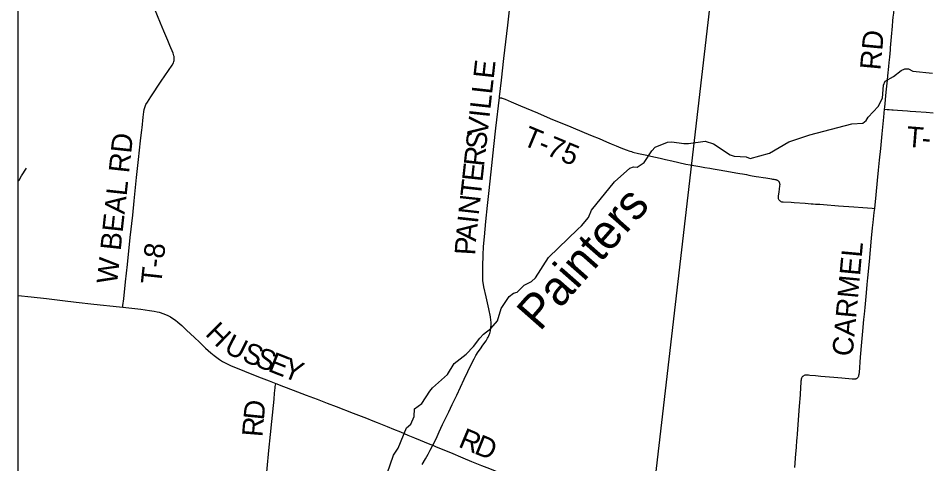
# Model space of a CAD drawing. Extents: x -49 to -8.2, y 9.4 to 23.5.
# Drawn here: x -14.966 to -13.706, y 10.403 to 11.018 of the extents above; entities that cross this region are included whole.
import ezdxf

# ---------------------------------------------------------------- set-up
doc = ezdxf.new("R2010")
doc.units = 0
for name, color, linetype in [('GM_X_Adjacent_County', 7, 'Continuous'), ('GM_X_County_Road', 7, 'Continuous'), ('GM_X_County_Road_Text', 7, 'Continuous'), ('GM_X_Minor_River', 7, 'Continuous'), ('GM_X_Minor_River_Text', 7, 'Continuous'), ('GM_X_Township_Road', 7, 'Continuous'), ('GM_X_Township_Road_Text', 7, 'Continuous')]:
    doc.layers.add(name, color=color, linetype=linetype)

msp = doc.modelspace()

# ---------------------------------------------------------------- linework, layer by layer
at = {"layer": 'GM_X_Adjacent_County'}
msp.add_lwpolyline([(-14.9662, 16.2087), (-8.1662, 16.2087), (-8.1662, 9.4087), (-14.9662, 9.4087)], close=True, dxfattribs=at)
msp.add_lwpolyline([(-14.005, 11.0879), (-14.0954, 10.3092), (-14.1248, 9.8722), (-14.156, 9.4087)], dxfattribs=at)
at = {"layer": 'GM_X_County_Road'}
for points in [[(-14.3018, 10.9084), (-14.3017, 10.9095), (-14.299, 10.9324), (-14.2954, 10.9626), (-14.29, 11.0083), (-14.2878, 11.029), (-14.2813, 11.0873), (-14.2771, 11.1259), (-14.2722, 11.171), (-14.2684, 11.205), (-14.2653, 11.2325), (-14.2624, 11.2587), (-14.258, 11.2986), (-14.2572, 11.3066)], [(-13.7697, 10.8924), (-13.7694, 10.895), (-13.7674, 10.916), (-13.7659, 10.9324), (-13.7653, 10.9386), (-13.764, 10.9512), (-13.7634, 10.9571), (-13.7627, 10.9642), (-13.7617, 10.9744), (-13.7614, 10.9772), (-13.7597, 10.9973), (-13.7593, 11.002), (-13.7588, 11.0072), (-13.7582, 11.0146), (-13.7578, 11.0193), (-13.7572, 11.0252), (-13.7562, 11.036), (-13.7553, 11.0455), (-13.7541, 11.0574)], [(-14.3937, 10.4284), (-14.3904, 10.4348), (-14.3877, 10.4407), (-14.3848, 10.4469), (-14.3801, 10.457), (-14.3717, 10.4747), (-14.3669, 10.4848), (-14.3607, 10.4977), (-14.3502, 10.5198), (-14.3453, 10.5302), (-14.3396, 10.542), (-14.3366, 10.5478), (-14.3341, 10.5523), (-14.331, 10.5575), (-14.3279, 10.5618), (-14.3244, 10.5666), (-14.3202, 10.5727), (-14.318, 10.5764), (-14.3171, 10.5778), (-14.3163, 10.5795), (-14.3158, 10.5809), (-14.3151, 10.5829), (-14.3146, 10.5845), (-14.3141, 10.5864), (-14.3138, 10.5881), (-14.3134, 10.5904), (-14.3131, 10.5947), (-14.313, 10.5964), (-14.3131, 10.5983), (-14.3134, 10.6014), (-14.3141, 10.606), (-14.3164, 10.6166), (-14.3202, 10.6336), (-14.3231, 10.6472), (-14.3241, 10.6531), (-14.3244, 10.6556), (-14.3246, 10.6577), (-14.3248, 10.6627), (-14.3246, 10.6758), (-14.3242, 10.691), (-14.3236, 10.7031), (-14.3225, 10.7162), (-14.3204, 10.7375), (-14.3181, 10.7594), (-14.316, 10.7801), (-14.3121, 10.8147), (-14.3092, 10.841), (-14.3065, 10.866), (-14.3018, 10.9084)], [(-13.7834, 10.7554), (-13.7814, 10.7744), (-13.7794, 10.7942), (-13.7781, 10.8081), (-13.7766, 10.822), (-13.775, 10.8381), (-13.7729, 10.8585), (-13.7707, 10.8814), (-13.7697, 10.8924)], [(-13.8937, 10.3977), (-13.8923, 10.4166), (-13.8916, 10.4252), (-13.8908, 10.4355), (-13.8906, 10.4379), (-13.8902, 10.4444), (-13.8872, 10.4825), (-13.886, 10.4983), (-13.8854, 10.5086), (-13.885, 10.5148), (-13.8849, 10.5176), (-13.8847, 10.5187), (-13.8845, 10.5201), (-13.8841, 10.5216), (-13.8836, 10.5227), (-13.883, 10.5234), (-13.8824, 10.5241), (-13.8817, 10.5246), (-13.8811, 10.5249), (-13.8805, 10.5252), (-13.8794, 10.5255), (-13.8781, 10.5257), (-13.8767, 10.5257), (-13.875, 10.5256), (-13.8729, 10.5253), (-13.8651, 10.5246), (-13.858, 10.524), (-13.84, 10.5225), (-13.8286, 10.5216), (-13.8143, 10.5202), (-13.8122, 10.5201), (-13.8103, 10.5202), (-13.8095, 10.5203), (-13.8088, 10.5206), (-13.8082, 10.5208), (-13.8075, 10.5212), (-13.807, 10.5216), (-13.8067, 10.5218), (-13.8063, 10.5225), (-13.8057, 10.5234), (-13.8055, 10.524), (-13.8052, 10.5251), (-13.8049, 10.5267), (-13.8045, 10.5291), (-13.8028, 10.5499), (-13.801, 10.571), (-13.7997, 10.5858), (-13.7982, 10.6019), (-13.7975, 10.6096), (-13.7966, 10.6186), (-13.7956, 10.6288), (-13.7947, 10.639), (-13.7936, 10.6504), (-13.7928, 10.6594), (-13.7908, 10.682), (-13.7878, 10.7145), (-13.7863, 10.7287), (-13.7855, 10.7361), (-13.784, 10.7497), (-13.7834, 10.7554)], [(-14.9662, 10.6353), (-14.9484, 10.6334), (-14.9271, 10.6309), (-14.9049, 10.6284), (-14.8864, 10.6262), (-14.862, 10.6234), (-14.8262, 10.6194), (-14.8218, 10.6189)], [(-14.8218, 10.6189), (-14.7971, 10.6162), (-14.7848, 10.6147), (-14.7787, 10.6137), (-14.7742, 10.6128), (-14.7716, 10.6122), (-14.77, 10.6117), (-14.7665, 10.6106), (-14.7627, 10.6091), (-14.7594, 10.6075), (-14.7561, 10.6057), (-14.7527, 10.6036), (-14.7492, 10.6011), (-14.7456, 10.5982), (-14.7405, 10.5937), (-14.7339, 10.5876), (-14.7227, 10.5772), (-14.7158, 10.5706), (-14.7074, 10.5627), (-14.7001, 10.556), (-14.6955, 10.5522), (-14.6921, 10.5495), (-14.6882, 10.5468), (-14.6843, 10.5443), (-14.6805, 10.5422), (-14.6768, 10.5403), (-14.672, 10.5382), (-14.6616, 10.534), (-14.6538, 10.5308), (-14.6342, 10.5229), (-14.6198, 10.5173), (-14.6104, 10.5138)], [(-14.6426, 10.2114), (-14.6409, 10.2244), (-14.6346, 10.2823), (-14.6303, 10.3221), (-14.6292, 10.3326), (-14.6276, 10.3481), (-14.6262, 10.361), (-14.6245, 10.3777), (-14.6225, 10.3966), (-14.62, 10.4213), (-14.6178, 10.4435), (-14.616, 10.4611), (-14.613, 10.4923), (-14.6122, 10.5004), (-14.6115, 10.5079), (-14.6113, 10.5098), (-14.611, 10.5114), (-14.6106, 10.5132), (-14.6104, 10.5138)], [(-14.6104, 10.5138), (-14.6, 10.5098), (-14.5864, 10.5046), (-14.5687, 10.4978), (-14.5536, 10.4921), (-14.5397, 10.4867), (-14.5272, 10.4819), (-14.5037, 10.4728), (-14.4853, 10.4657), (-14.4764, 10.4624), (-14.4707, 10.4601), (-14.4566, 10.4543), (-14.448, 10.4508), (-14.4382, 10.4468), (-14.4281, 10.4426), (-14.419, 10.4388), (-14.3978, 10.4301), (-14.3937, 10.4284)], [(-14.4084, 10.4018), (-14.4039, 10.4097), (-14.4002, 10.4161), (-14.3971, 10.4218), (-14.3937, 10.4284)], [(-14.3937, 10.4284), (-14.3892, 10.4265), (-14.3693, 10.4184), (-14.3521, 10.4112), (-14.3401, 10.4062), (-14.3266, 10.4007), (-14.3156, 10.3962), (-14.3076, 10.393), (-14.2945, 10.3878), (-14.2771, 10.3811), (-14.2556, 10.373), (-14.2295, 10.3631), (-14.2123, 10.3567), (-14.2027, 10.3531), (-14.1797, 10.3445), (-14.162, 10.3378), (-14.1306, 10.326), (-14.1094, 10.318), (-14.0942, 10.3124), (-14.093, 10.3119)]]:
    msp.add_lwpolyline(points, dxfattribs=at)
at = {"layer": 'GM_X_Minor_River'}
for points in [[(-14.0914, 10.8349), (-14.0865, 10.84), (-14.0695, 10.847), (-14.0634, 10.8475), (-14.0468, 10.8452), (-14.0405, 10.8449), (-14.0177, 10.8484), (-14.006, 10.8446), (-13.983, 10.8295), (-13.9774, 10.8274), (-13.9607, 10.8266), (-13.9556, 10.8244), (-13.9289, 10.8315), (-13.902, 10.8473), (-13.8729, 10.8571), (-13.8152, 10.872), (-13.7999, 10.8733), (-13.7951, 10.8766), (-13.7926, 10.8815), (-13.7787, 10.8962), (-13.7725, 10.9077), (-13.7712, 10.9257), (-13.769, 10.9312), (-13.7574, 10.9376), (-13.747, 10.9457), (-13.7417, 10.9481), (-13.7369, 10.948), (-13.7309, 10.9451), (-13.7036, 10.9421)], [(-14.4566, 10.3897), (-14.4481, 10.4148), (-14.4417, 10.4246), (-14.43, 10.4527), (-14.4241, 10.4578), (-14.4194, 10.4682), (-14.4189, 10.4788), (-14.409, 10.4861), (-14.3979, 10.503), (-14.3943, 10.5079), (-14.3732, 10.5264), (-14.3643, 10.5413), (-14.3478, 10.5542), (-14.3373, 10.5647), (-14.3286, 10.5763), (-14.3238, 10.5817), (-14.3135, 10.5896), (-14.3042, 10.6003), (-14.2993, 10.6173), (-14.2883, 10.6339), (-14.2823, 10.6383), (-14.2772, 10.6398), (-14.2674, 10.6497), (-14.2573, 10.6545), (-14.2517, 10.6594), (-14.2339, 10.6876), (-14.1935, 10.7268), (-14.1885, 10.7312), (-14.1788, 10.7427), (-14.1744, 10.7529), (-14.1428, 10.7923), (-14.1217, 10.8109), (-14.1167, 10.8127), (-14.1116, 10.8124), (-14.1017, 10.8188), (-14.0914, 10.8349)], [(-14.9662, 10.7932), (-14.9648, 10.7944), (-14.9619, 10.8002), (-14.9547, 10.8108)]]:
    msp.add_lwpolyline(points, dxfattribs=at)
at = {"layer": 'GM_X_Township_Road'}
for points in [[(-14.7955, 10.864), (-14.7952, 10.8667), (-14.7937, 10.8812), (-14.7928, 10.8889), (-14.7923, 10.8918), (-14.7919, 10.8934), (-14.7916, 10.8948), (-14.7911, 10.8962), (-14.7905, 10.8974), (-14.7899, 10.8987), (-14.7879, 10.9022), (-14.7833, 10.9096), (-14.7687, 10.9312), (-14.7538, 10.9534), (-14.7519, 10.9566), (-14.7512, 10.9582), (-14.7509, 10.9595), (-14.7508, 10.9604), (-14.7507, 10.9613), (-14.7507, 10.9623), (-14.7507, 10.9632), (-14.7508, 10.9641), (-14.751, 10.9651), (-14.7513, 10.9663), (-14.7523, 10.9696), (-14.7569, 10.9805), (-14.7598, 10.9874), (-14.7651, 11.0003), (-14.7698, 11.0114), (-14.778, 11.0316)], [(-14.3018, 10.9084), (-14.3013, 10.9083), (-14.2995, 10.908), (-14.299, 10.9079), (-14.2983, 10.9077), (-14.2978, 10.9075), (-14.2939, 10.9061), (-14.2856, 10.9026), (-14.2724, 10.8971), (-14.249, 10.8872), (-14.2315, 10.8798), (-14.2031, 10.868), (-14.1848, 10.8603), (-14.1738, 10.8558), (-14.1641, 10.8518), (-14.1538, 10.8474), (-14.1472, 10.8447), (-14.1403, 10.8418), (-14.134, 10.8392), (-14.1265, 10.8361), (-14.1215, 10.8344), (-14.1195, 10.8338), (-14.1174, 10.8332), (-14.1095, 10.8313), (-14.098, 10.8288), (-14.0925, 10.8275), (-14.0795, 10.8246), (-14.0725, 10.8231), (-14.0635, 10.8211), (-14.0444, 10.8167), (-14.0384, 10.8156), (-14.0379, 10.8155)], [(-13.7697, 10.8924), (-13.7662, 10.8922), (-13.7657, 10.8922), (-13.7648, 10.8921), (-13.7633, 10.892), (-13.7599, 10.8917), (-13.758, 10.8916), (-13.7518, 10.8911), (-13.7379, 10.89), (-13.7345, 10.8898), (-13.7267, 10.8892), (-13.7122, 10.8881), (-13.7026, 10.8873)], [(-14.8218, 10.6189), (-14.8216, 10.6212), (-14.8205, 10.6306), (-14.818, 10.6541), (-14.8154, 10.6779), (-14.8115, 10.7153), (-14.8081, 10.7462), (-14.8061, 10.7657), (-14.8027, 10.7981), (-14.8, 10.8231), (-14.7972, 10.8488), (-14.7955, 10.864)], [(-14.0379, 10.8155), (-14.0332, 10.8146), (-14.0248, 10.8132), (-14.018, 10.8121), (-14.0113, 10.811), (-14.0066, 10.8102), (-14.0009, 10.8091), (-13.9878, 10.8067), (-13.9751, 10.8045), (-13.9698, 10.8037), (-13.966, 10.803), (-13.9606, 10.8021), (-13.9573, 10.8015), (-13.9549, 10.801), (-13.9525, 10.8006), (-13.947, 10.7996), (-13.9434, 10.799), (-13.9375, 10.7981), (-13.9338, 10.7975), (-13.9283, 10.7966), (-13.9259, 10.7962), (-13.9246, 10.796), (-13.9225, 10.7957), (-13.9212, 10.7955), (-13.9201, 10.7952), (-13.9194, 10.795), (-13.9186, 10.7947), (-13.9179, 10.7944), (-13.9172, 10.794), (-13.9167, 10.7935), (-13.9163, 10.7931), (-13.9157, 10.7924), (-13.9155, 10.792), (-13.9152, 10.7913), (-13.9149, 10.7907), (-13.9147, 10.7898), (-13.9146, 10.7883), (-13.9147, 10.7867), (-13.9153, 10.7821), (-13.9159, 10.7784), (-13.9167, 10.7723), (-13.9167, 10.771), (-13.9167, 10.7701), (-13.9166, 10.7692), (-13.9163, 10.7683), (-13.916, 10.7676), (-13.9155, 10.767), (-13.9151, 10.7665), (-13.9141, 10.7657), (-13.9136, 10.7654), (-13.913, 10.7651), (-13.9119, 10.7647), (-13.9111, 10.7645), (-13.91, 10.7644), (-13.8988, 10.7639), (-13.8945, 10.7636), (-13.8796, 10.7627), (-13.8713, 10.762), (-13.8682, 10.7618), (-13.8651, 10.7615), (-13.862, 10.7613), (-13.8592, 10.7611), (-13.8539, 10.7607), (-13.8335, 10.7591), (-13.8124, 10.7575), (-13.8, 10.7566), (-13.787, 10.7557), (-13.7834, 10.7554)]]:
    msp.add_lwpolyline(points, dxfattribs=at)

# ---------------------------------------------------------------- texts
at = {"layer": 'GM_X_County_Road_Text'}
for s, height, rotation, p in [('RD', 0.02841, 84.6735, (-13.7756, 10.9456)), ('E', 0.0284, 83.7346, (-14.3096, 10.9336)), ('L', 0.0284, 83.7346, (-14.3119, 10.9124)), ('L', 0.0284, 83.7346, (-14.3142, 10.8913)), ('I', 0.0284, 83.7348, (-14.3155, 10.8797)), ('V', 0.0284, 83.733, (-14.3182, 10.8549)), ('S', 0.0284, 83.7348, (-14.3203, 10.8358)), ('R', 0.0284, 83.7348, (-14.3229, 10.8126)), ('E', 0.0284, 83.735, (-14.3252, 10.7915)), ('T', 0.0284, 83.7377, (-14.3275, 10.7704)), ('N', 0.0284, 83.734, (-14.3303, 10.7455)), ('I', 0.0284, 83.727, (-14.3315, 10.7339)), ('A', 0.0284, 84.0697, (-14.3341, 10.7091)), ('P', 0.0284, 86.4435, (-14.3353, 10.6903)), ('CARMEL', 0.02841, 84.7308, (-13.814, 10.5505)), ('H', 0.0284, 315.1803, (-14.7091, 10.5811)), ('U', 0.0284, 333.105, (-14.6835, 10.5578)), ('S', 0.0284, 338.8396, (-14.6584, 10.5453)), ('S', 0.0284, 338.6142, (-14.6405, 10.5384)), ('E', 0.0284, 338.6174, (-14.6227, 10.5314)), ('Y', 0.0284, 338.6179, (-14.6029, 10.5236)), ('D', 0.0284, 84.1981, (-14.6271, 10.4624)), ('R', 0.0284, 85.3386, (-14.629, 10.4393)), ('R', 0.0284, 337.1327, (-14.3597, 10.4269)), ('D', 0.0284, 338.071, (-14.3378, 10.4176))]:
    msp.add_text(s, height=height, rotation=rotation, dxfattribs=at).set_placement(p)
at = {"layer": 'GM_X_Minor_River_Text'}
msp.add_text('Painters', height=0.04734, rotation=48.6343, dxfattribs=at).set_placement((-14.2459, 10.5846))
at = {"layer": 'GM_X_Township_Road_Text'}
for s, height, rotation, p in [('T-75', 0.02841, 337.3597, (-14.2714, 10.8437)), ('T', 0.0284, 355.3666, (-13.7404, 10.8407)), ('W BEAL RD', 0.02841, 83.826, (-14.8298, 10.6502)), ('-', 0.0284, 355.395, (-13.7192, 10.839)), ('T-8', 0.02841, 83.8168, (-14.7688, 10.6496))]:
    msp.add_text(s, height=height, rotation=rotation, dxfattribs=at).set_placement(p)

doc.saveas('drawing.dxf')
